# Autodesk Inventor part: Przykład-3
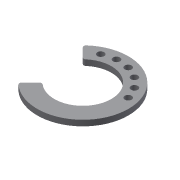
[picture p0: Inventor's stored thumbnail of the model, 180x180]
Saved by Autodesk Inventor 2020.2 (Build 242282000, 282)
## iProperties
Created: 2006-03
Part Number: Przykład-3
Document SubType Name: Modeling
Designer: F.Stasiak
Density: 1 g/cm^3
Material: Ogólny
Appearance: Domyślna
Manager: www.cadconsulting.pl
Company: Fabian Stasiak CAD Consulting
Author: F.Stasiak
Subject: Zbiór ćwiczeń. Autodesk Inventor 2020. Kurs podstawowy
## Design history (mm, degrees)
sketch "Szkic1"
  geometry: L1 (0, 0)-(-28.284, 28.284); L2 (0, 0)-(-28.284, -28.284); L3 (-35.113, 0)-(60.485, 0) reference; A1 r 40 centre (0, 0) between (-28.284, -28.284) and (-28.284, 28.284); A2 r 25 centre (0, 0) between (-17.678, -17.678) and (-17.678, 17.678); 1 further point
  constraints: 4 end point, 4 point on circle, 2 centre point, 2 coincident, 2 point on line
  dimensions: "d0" = 80 diameter of A1; "d1" = 50 diameter of A2; "d2" = 90 deg angle of L2 L1; "d3" = 45 deg angle of L1 L3 (= 0.5 x d2)
extrude "Wyciągnięcie proste1" new body sketch "Szkic1" distance "d4" = 5; taper "d5" = 0 deg
sketch "Szkic2"
  geometry: L1 (-17.678, 17.678)-(-28.284, 28.284) reference; L2 (-13.735, 29.455)-(0, 0); A1 r 25 centre (0, 0) between (-17.678, -17.678) and (-17.678, 17.678) reference; A2 r 32.5 centre (0, 0) between (-22.981, -22.981) and (-22.981, 22.981)
  constraints: 3 point on circle, 2 end point, 1 centre point, 1 midpoint
  dimensions: "KĄT" = 20 deg angle of L1 L2
hole "Otwór1" sketch "Szkic2" at (-13.735, 29.455) diameter "d7" = 6; stored, may be unused: drill point angle "d13" = 118 deg, countersink angle "d22" = 90 deg; dims "d12" = 8, "d19" = 6, "d20" = 4, "d21" = 2
fillet "Zaokrąglenie1" dims "d8" = 2
pattern_circular "Szyk kołowy2" dims angle "d24" = 100 deg (computed from L_OTWORÓW, KĄT)
node "Bryła1"
node "Korpusy bryłowe"
node "Korpusy powierzchniowe"
